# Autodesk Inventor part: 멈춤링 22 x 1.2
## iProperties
IsCustomPart: 0
Company: 한국ATC센터
Created: 2014-07
Part Number: 멈춤링 22 x 1.2
Material: Steel, Mild
Description: 리테이닝 링(C형)
Document SubType Name: Modeling
Standard: KS B 1336
Designer: KYOUNG IL JANG
Standards Organization: KS
Language: ko-KR
Size Designation: 22 x 1.2
Categories: <MemberInstance><Categories><Category DisplayName="샤프트 부품" InternalName="7f7aeb1f-a693-4053-b835-cee3144e0d98" Mnemonic="SHFT"><Category DisplayName="써클립" Inter
Density: 1 g/cm^3
Author: KYOUNG IL JANG
